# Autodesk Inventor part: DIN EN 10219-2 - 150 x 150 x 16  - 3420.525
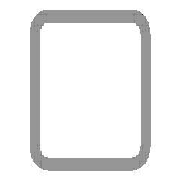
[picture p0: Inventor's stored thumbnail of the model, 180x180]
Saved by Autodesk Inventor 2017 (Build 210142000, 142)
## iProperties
IsCustomPart: 1
Created: 2017-11
Part Number: DIN EN 10219-2 - 150 x 150 x 16  - 3420.525
Material: Steel, Mild
Description: Cold formed welded structural hollow sections of non-alloy and fine grain structural steel
Document SubType Name: Modeling
Standard: DIN
Designer: iusti
Standard Revision: 2006-07
Standards Organization: DIN
Language: en-US
Size Designation: 150 x 150 x 16
Categories: <MemberInstance><Categories><Category DisplayName="Structural Shapes" InternalName="089c4875-fa83-4c05-b084-43b9cc11f5ed" Mnemonic="GRDR"><CategoryParameter Dis
Stock Number: 150 x 150 x 16
Density: 7.85 g/cm^3
Appearance: Semi-Polished
Mass: 187715 g
Surface Area: 30177.9 cm^2
Volume: 23912.8 cm^3
_CCFamilyMember: 76
_CCFamilyDisplayName: DIN EN 10219-2 (Square Hollow Section - Cold Formed) - Cold formed welded structural hollow sections of non-alloy and fine grain structural steel
_FrameMemberDoc: Frame Member File
_Version: 15.0.0
_GetPNFromCC: 1
G_L: 3420.525 mm
G_W: 150.000 mm
G_H: 150.000 mm
+C5A7F213-7B8F-416C-AD71-AED6F988D7A0+CUTDETAIL1: Cut
+92DA0260-704C-43BE-8B8B-0C986C6355A8+CUTDETAIL2: Cut
Author: iusti
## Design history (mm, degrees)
node "Start plane"
node "End plane"
sketch "Sketch"
  geometry: L1 (-75, -27)-(-75, 27); L2 (-27, 75)-(27, 75); L3 (75, 27)-(75, -27); L4 (27, -75)-(-27, -75); L5 (-27, 59)-(27, 59); L6 (59, 27)-(59, -27); L7 (27, -59)-(-27, -59); L8 (-59, -27)-(-59, 27); L9 (0, 118.918)-(0, -118.918) reference; L10 (-118.918, 0)-(118.918, 0) reference; A1 r 48 centre (-27, -27) between (-75, -27) and (-27, -75); A2 r 48 centre (-27, 27) between (-27, 75) and (-75, 27); A3 r 48 centre (27, 27) between (75, 27) and (27, 75); A4 r 48 centre (27, -27) between (27, -75) and (75, -27); A5 r 32 centre (-27, 27) between (-27, 59) and (-59, 27); A6 r 32 centre (27, 27) between (59, 27) and (27, 59); A7 r 32 centre (27, -27) between (27, -59) and (59, -27); A8 r 32 centre (-27, -27) between (-59, -27) and (-27, -59)
  constraints: 16 end point, 16 point on circle, 8 centre point, 8 tangent, 4 parallel, 3 equal radius, 2 perpendicular, 7 other
  dimensions: "d7" = 48 radius of A1 (= G_IR); "d10" = 150 distance between parallel lines of L2 L4 (= G_H); "d11" = 150 distance between parallel lines of L1 L3 (= G_W); "d12" = 16 distance between parallel lines of L3 L6 (= G_T); "d15" = 75 distance between parallel lines of L2 L10 (= 0.5 x d10); "d16" = 75 distance between parallel lines of L9 L3 (= 0.5 x d11)
extrude "Body" new body sketch "Sketch" stored distance "d3" = 3420.52498 (= G_L); taper "d4" = 0 deg
node "Driven Length"
  sketch "Sketch3"
    geometry: L1 (0, 0)-(10, 0) reference
    constraints: 2 end point, 1 horizontal
  workplane "Work Plane3"
  sketch "Sketch4"
    geometry: L1 (-2, 22.056)-(12, 22.056) reference; L2 (-2, 3442.581)-(12, 3442.581) reference
    dimensions: "d18" = 3420.52498 distance between parallel lines of L1 L2 (derived)
workplane "Work Plane4"
split "Split1"
workplane "Work Plane5"
split "Split2"
body "Solid1"
other parameters: "G_W" = 150 [user parameter; used in 1 equation term], "G_H" = 150 [user parameter; used in 1 equation term], "G_T" = 16 [user parameter; used in 1 equation term], "G_IR" = 48 [user parameter; used in 1 equation term], "G_L" = 3420.52498 (= d18) [user parameter; used in 1 equation term], "G_OFFSET_START" = -22.05576 [user parameter; used in 1 equation term], "G_OFFSET_END" = -14.0359 [user parameter; used in 1 equation term], "d13" = 22.05576 (= -G_OFFSET_START), "d14" = 3442.58074 (= G_OFFSET_END + B_L), "B_L" = 3456.61664 [user parameter; used in 1 equation term], "d17" = 90 deg
